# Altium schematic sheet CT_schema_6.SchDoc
size 304 x 319 mm
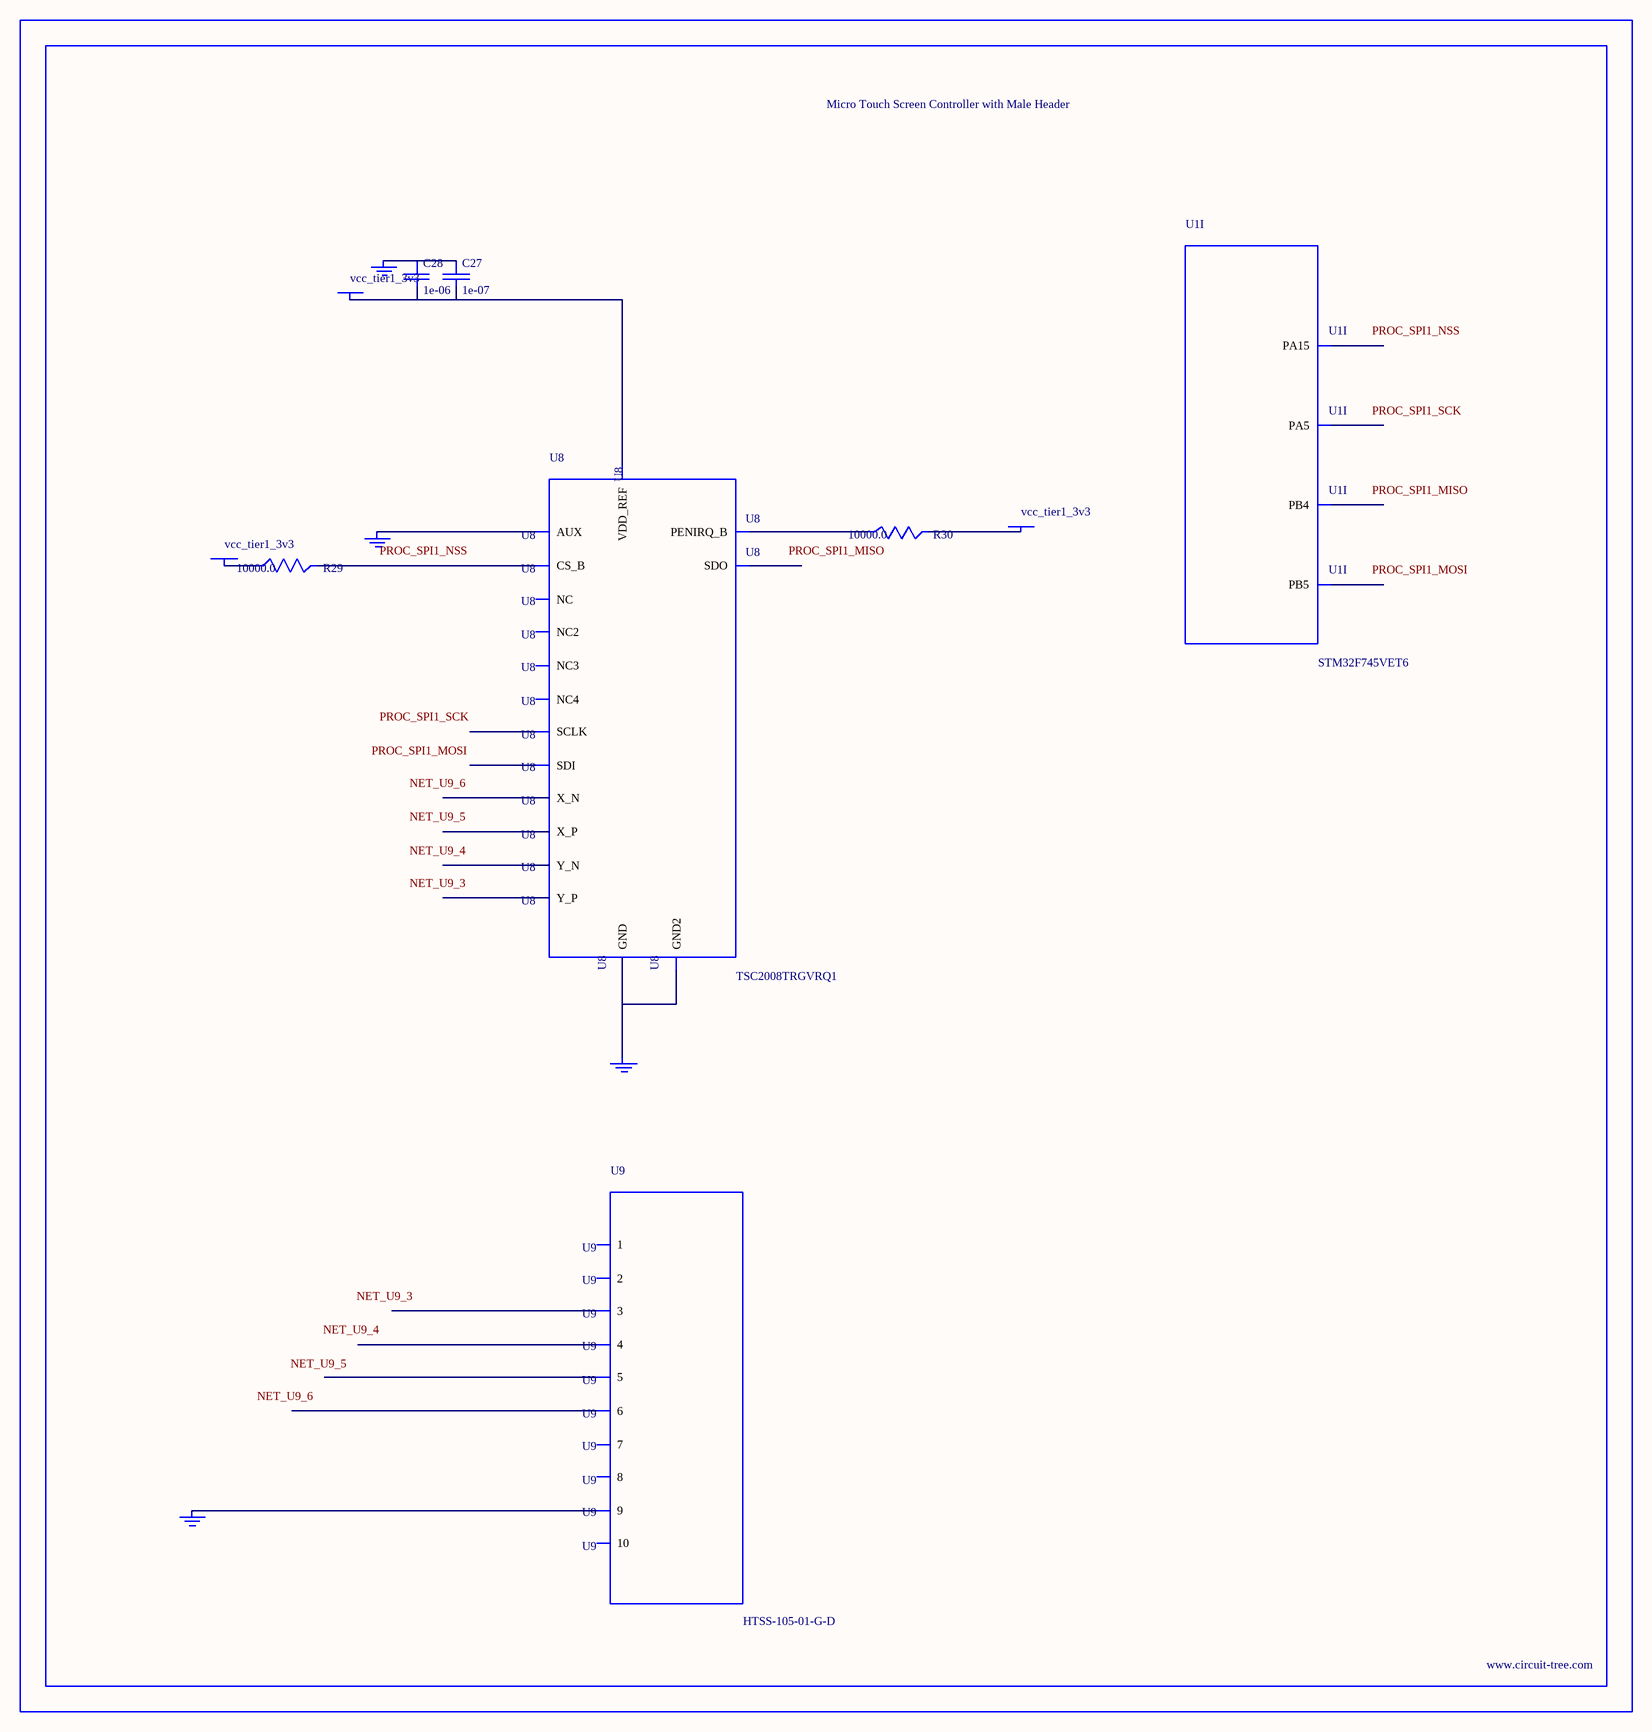
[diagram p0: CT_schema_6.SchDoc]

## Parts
BORDER5  (no value)
C27  1e-07  [C0402]
C28  1e-06  [C0603]
GND_INSTANCE_5_0  (no value)
GND_INSTANCE_5_1  (no value)
GND_INSTANCE_5_2  (no value)
GND_INSTANCE_5_3  (no value)
POWER_INSTANCE_5_0  vcc_tier1_3v3
POWER_INSTANCE_5_1  vcc_tier1_3v3
POWER_INSTANCE_5_2  vcc_tier1_3v3
R29  10000.0  [R0603]
R30  10000.0  [R0603]
U1  STM32F745VET6  [LQFP100]  (part I of 9)
U8  TSC2008TRGVRQ1  [QFN65P400X400X100-17N]
U9  HTSS-105-01-G-D  [HTSS-105-01-G-D]

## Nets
NetC27_1: C27.1 C28.1 GND_INSTANCE_5_0.0(GND)
NetC27_2: C27.2 C28.2 POWER_INSTANCE_5_1.0(PWR) U8.5(VDD_REF)
NetGND_INSTANCE_5_1_0: GND_INSTANCE_5_1.0(GND) U8.12(AUX)
NetGND_INSTANCE_5_2_0: GND_INSTANCE_5_2.0(GND) U8.10(GND) U8.17(GND2)
NetGND_INSTANCE_5_3_0: GND_INSTANCE_5_3.0(GND) U9.9
NetPOWER_INSTANCE_5_0_0: POWER_INSTANCE_5_0.0(PWR) R29.1
NetPOWER_INSTANCE_5_2_0: POWER_INSTANCE_5_2.0(PWR) R30.2
NetR29_2: R29.2 U8.3(CS_B)
NetR30_1: R30.1 U8.15(PENIRQ_B)

Not connected (* = marked no-connect by the designer): U1 29(PA5) 77(PA15) 90(PB4) 91(PB5); U8 1(NC) 2(SDI) 4(SCLK) 6(X_P) 7(Y_P) 8(X_N) 9(Y_N) 11(NC2) 13(NC3) 14(NC4) 16(SDO); U9 1 2 3 4 5 6 7 8 10

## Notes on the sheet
- Labels drawn without touching a wire or pin: NET_U9_3, NET_U9_4, NET_U9_5, NET_U9_6, PROC_SPI1_MISO, PROC_SPI1_MOSI, PROC_SPI1_NSS, PROC_SPI1_SCK

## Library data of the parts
BORDER5 = BORDER_PAGE5
C27 = C0402C104K3RACTU
C28 = C0603C105K3RACTU
GND_INSTANCE_5_0-GND_INSTANCE_5_3 = GND
POWER_INSTANCE_5_0-POWER_INSTANCE_5_2 = PWR
R29 R30 = RC0603JR-0710KL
